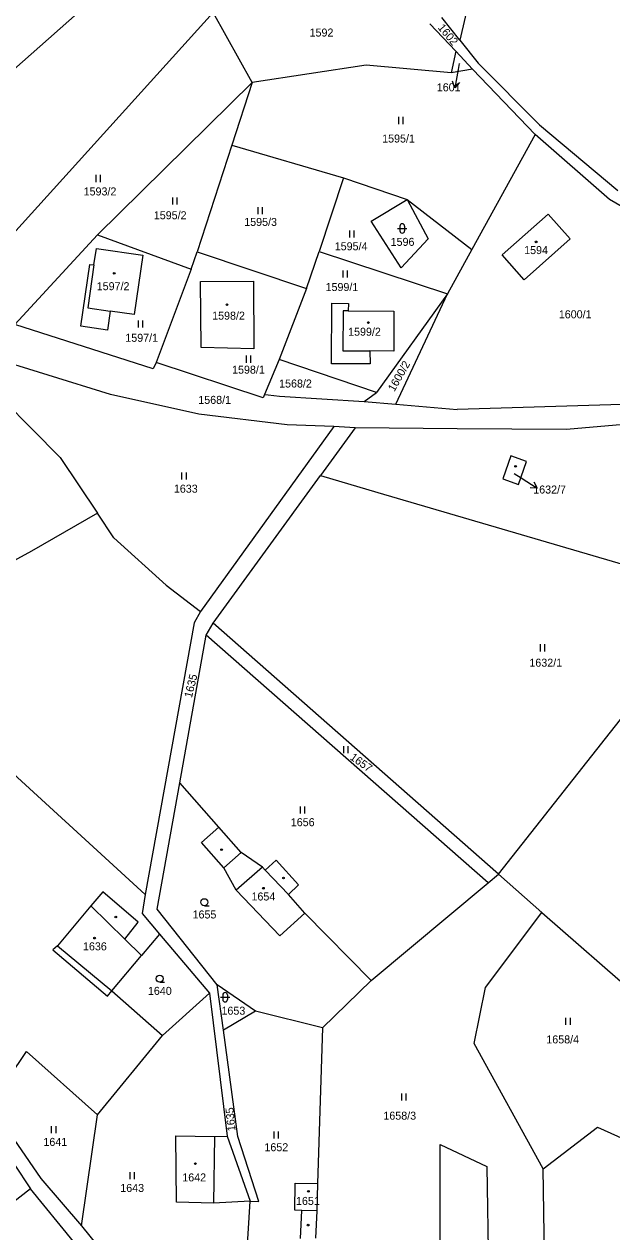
# Model space of a CAD drawing. Extents: x -670359 to -668019, y -978807 to -976674.
# Drawn here: x -669263 to -669138.3, y -978307.2 to -978050.6 of the extents above; entities that cross this region are included whole.
import ezdxf

# ---------------------------------------------------------------- set-up
doc = ezdxf.new("R2010")
doc.units = 0
for name, color, linetype in [('Hranice parcel', 7, 'Continuous'), ('Parcelní čísla', 7, 'Continuous'), ('Vnitřní kresba', 7, 'Continuous'), ('Značky budov', 7, 'Continuous'), ('Značky kultur', 7, 'Continuous')]:
    doc.layers.add(name, color=color, linetype=linetype)

msp = doc.modelspace()

# ---------------------------------------------------------------- linework, layer by layer
at = {"layer": 'Hranice parcel'}
for p, q in [((-669197.76, -978122.79), (-669197.75, -978109.9)), ((-669197.75, -978109.9), (-669194.2, -978109.99)), ((-669194.2, -978109.99), (-669194.25, -978111.55)), ((-669184.14, -978131.34), (-669173.14, -978107.89)), ((-669194.25, -978111.55), (-669184.52, -978111.61)), ((-669184.52, -978111.61), (-669184.54, -978120.13)), ((-669184.54, -978120.13), (-669189.62, -978120.06)), ((-669189.62, -978120.06), (-669189.6, -978122.82)), ((-669189.6, -978122.82), (-669197.76, -978122.79)), ((-669190.87, -978130.76), (-669184.14, -978131.34)), ((-669184.14, -978131.34), (-669171.08, -978132.47)), ((-669153.11, -978239.3), (-669162.35, -978231.21)), ((-669165.06, -978255.27), (-669153.11, -978239.3)), ((-669153.11, -978239.3), (-669114.29, -978273.3)), ((-669167.46, -978267.15), (-669165.06, -978255.27)), ((-669152.85, -978293.75), (-669167.46, -978267.15))]:
    msp.add_line(p, q, dxfattribs=at)
for points in [[(-669162.99, -978021.31), (-669170.57, -978054.01)], [(-669234.55, -978033), (-669307.7, -978097.77)], [(-669280.17, -978111.46), (-669222.94, -978048.17)], [(-669214.62, -978063.05), (-669222.94, -978048.17)], [(-669171.4, -978056.4), (-669176.94, -978050.58)], [(-669170.57, -978054.01), (-669174.37, -978049.25)], [(-669171.4, -978056.4), (-669172.41, -978060.95)], [(-669167.84, -978060.2), (-669171.4, -978056.4)], [(-669170.57, -978054.01), (-669166.62, -978058.93)], [(-669166.62, -978058.93), (-669153.63, -978072.03)], [(-669190.4, -978059.32), (-669214.62, -978063.05)], [(-669172.41, -978060.95), (-669190.4, -978059.32)], [(-669167.84, -978060.2), (-669172.41, -978060.95)], [(-669154.54, -978074.1), (-669167.84, -978060.2)], [(-669214.62, -978063.05), (-669247.46, -978095.41)], [(-669214.62, -978063.05), (-669218.93, -978076.33)], [(-669154.54, -978074.1), (-669167.96, -978098.48)], [(-669138.75, -978087.87), (-669154.54, -978074.1)], [(-669153.63, -978072.03), (-669136.97, -978085.97)], [(-669218.93, -978076.33), (-669226.28, -978099)], [(-669218.93, -978076.33), (-669195.22, -978083.25)], [(-669195.22, -978083.25), (-669200.43, -978098.96)], [(-669195.22, -978083.25), (-669181.74, -978087.88)], [(-669189.39, -978092.52), (-669181.74, -978087.88)], [(-669181.74, -978087.88), (-669167.96, -978098.48)], [(-669181.74, -978087.88), (-669177.26, -978096.25)], [(-669123.24, -978096.91), (-669138.75, -978087.87)], [(-669161.57, -978099.66), (-669151.75, -978090.97)], [(-669151.75, -978090.97), (-669147.09, -978096.22)], [(-669183.01, -978102.43), (-669189.39, -978092.52)], [(-669247.46, -978095.41), (-669265.03, -978114.42)], [(-669247.46, -978095.41), (-669227.6, -978102.67)], [(-669177.26, -978096.25), (-669183.01, -978102.43)], [(-669147.09, -978096.22), (-669156.86, -978104.95)], [(-669248.23, -978101.77), (-669247.72, -978098.27)], [(-669247.72, -978098.27), (-669237.84, -978099.69)], [(-669237.84, -978099.69), (-669239.66, -978112.34)], [(-669227.6, -978102.67), (-669226.28, -978099)], [(-669226.28, -978099), (-669203.07, -978106.77)], [(-669203.07, -978106.77), (-669200.43, -978098.96)], [(-669200.43, -978098.96), (-669173.14, -978107.89)], [(-669167.96, -978098.48), (-669173.14, -978107.89)], [(-669156.86, -978104.95), (-669161.57, -978099.66)], [(-669251.01, -978114.77), (-669249.11, -978101.66)], [(-669249.11, -978101.66), (-669248.23, -978101.77)], [(-669227.6, -978102.67), (-669235.02, -978122.5)], [(-669225.63, -978105.33), (-669214.34, -978105.21)], [(-669214.34, -978105.21), (-669214.29, -978119.57)], [(-669225.46, -978119.29), (-669225.63, -978105.33)], [(-669203.07, -978106.77), (-669208.91, -978121.9)], [(-669173.14, -978107.89), (-669188.25, -978128.85)], [(-669244.82, -978111.6), (-669245.38, -978115.62)], [(-669239.66, -978112.34), (-669244.82, -978111.6)], [(-669235.67, -978123.85), (-669265.03, -978114.42)], [(-669245.38, -978115.62), (-669251.01, -978114.77)], [(-669214.29, -978119.57), (-669225.46, -978119.29)], [(-669244.69, -978129.28), (-669271.26, -978121.07)], [(-669235.02, -978122.5), (-669235.67, -978123.85)], [(-669212.28, -978130.03), (-669235.02, -978122.5)], [(-669208.91, -978121.9), (-669211.98, -978129.3)], [(-669188.25, -978128.85), (-669208.91, -978121.9)], [(-669273.38, -978124.57), (-669255.4, -978142.68)], [(-669225.93, -978133.48), (-669244.69, -978129.28)], [(-669211.98, -978129.3), (-669212.28, -978130.03)], [(-669211.98, -978129.3), (-669211.25, -978129.4), (-669208.86, -978129.64), (-669190.87, -978130.76)], [(-669190.87, -978130.76), (-669188.25, -978128.85)], [(-669136.17, -978131.41), (-669171.08, -978132.47)], [(-669207.22, -978135.76), (-669225.93, -978133.48)], [(-669197.3, -978136.11), (-669207.22, -978135.76)], [(-669135.74, -978135.65), (-669147.91, -978136.72)], [(-669197.3, -978136.11), (-669225.57, -978175.39)], [(-669192.74, -978136.4), (-669200.12, -978146.54)], [(-669192.74, -978136.4), (-669197.3, -978136.11)], [(-669171.13, -978136.63), (-669192.74, -978136.4)], [(-669147.91, -978136.72), (-669171.13, -978136.63)], [(-669255.4, -978142.68), (-669247.51, -978154.5)], [(-669159.68, -978142.35), (-669161.4, -978147.2)], [(-669156.38, -978143.57), (-669159.68, -978142.35)], [(-669158.06, -978148.39), (-669156.38, -978143.57)], [(-669222.95, -978177.9), (-669200.12, -978146.54)], [(-669200.12, -978146.54), (-669187.92, -978150.12)], [(-669161.4, -978147.2), (-669158.06, -978148.39)], [(-669187.92, -978150.12), (-669122.96, -978169.18)], [(-669247.51, -978154.5), (-669261.49, -978162.57)], [(-669244.01, -978159.74), (-669247.51, -978154.5)], [(-669244.01, -978159.74), (-669232.87, -978169.8)], [(-669261.49, -978162.57), (-669288.18, -978177.2)], [(-669232.87, -978169.8), (-669225.57, -978175.39)], [(-669225.57, -978175.39), (-669226.95, -978177.78)], [(-669226.95, -978177.78), (-669237.33, -978235.49)], [(-669224.42, -978180.44), (-669222.95, -978177.9)], [(-669162.35, -978231.21), (-669222.95, -978177.9)], [(-669230.01, -978211.78), (-669224.42, -978180.44)], [(-669164.49, -978233), (-669224.42, -978180.44)], [(-669162.35, -978231.21), (-669134.61, -978195.97)], [(-669271.34, -978204.41), (-669237.33, -978235.49)], [(-669234.8, -978238.64), (-669230.01, -978211.78)], [(-669221.7, -978221.23), (-669230.01, -978211.78)], [(-669225.38, -978224.47), (-669221.7, -978221.23)], [(-669216.98, -978226.6), (-669221.7, -978221.23)], [(-669220.66, -978229.84), (-669225.38, -978224.47)], [(-669212.45, -978229.68), (-669216.98, -978226.6)], [(-669209.56, -978228.2), (-669211.9, -978230.33)], [(-669204.81, -978233.45), (-669209.56, -978228.2)], [(-669218.03, -978234.58), (-669220.66, -978229.84)], [(-669211.9, -978230.33), (-669212.45, -978229.68)], [(-669206.91, -978235.5), (-669204.81, -978233.45)], [(-669189.33, -978253.77), (-669164.49, -978233)], [(-669164.49, -978233), (-669162.35, -978231.21)], [(-669246.37, -978234.92), (-669248.88, -978237.93)], [(-669238.83, -978241.4), (-669246.37, -978234.92)], [(-669237.33, -978235.49), (-669238.01, -978239.57)], [(-669208.76, -978244.28), (-669218.03, -978234.58)], [(-669203.43, -978239.46), (-669206.91, -978235.5)], [(-669248.88, -978237.93), (-669255.94, -978246.41)], [(-669238.01, -978239.57), (-669234.31, -978243.93)], [(-669222.08, -978254.7), (-669234.8, -978238.64)], [(-669203.43, -978239.46), (-669208.76, -978244.28)], [(-669189.33, -978253.77), (-669203.43, -978239.46)], [(-669241.67, -978244.97), (-669238.83, -978241.4)], [(-669238.11, -978248.44), (-669241.67, -978244.97)], [(-669234.31, -978243.93), (-669238.11, -978248.44)], [(-669234.31, -978243.93), (-669223.7, -978256.44)], [(-669255.94, -978246.41), (-669256.99, -978247.28)], [(-669256.99, -978247.28), (-669245.32, -978257.08)], [(-669244.43, -978255.97), (-669238.11, -978248.44)], [(-669199.68, -978263.84), (-669189.33, -978253.77)], [(-669245.32, -978257.08), (-669244.43, -978255.97)], [(-669244.43, -978255.97), (-669233.64, -978265.45)], [(-669233.64, -978265.45), (-669223.7, -978256.44)], [(-669223.7, -978256.44), (-669219.94, -978286.87)], [(-669213.9, -978260.3), (-669222.08, -978254.7)], [(-669220.74, -978264.31), (-669222.08, -978254.7)], [(-669213.9, -978260.3), (-669220.74, -978264.31)], [(-669199.68, -978263.84), (-669213.9, -978260.3)], [(-669199.68, -978263.84), (-669200.76, -978296.92)], [(-669247.51, -978282.34), (-669233.64, -978265.45)], [(-669217.7, -978286.9), (-669220.74, -978264.31)], [(-669270.3, -978280.25), (-669262.58, -978268.89)], [(-669262.58, -978268.89), (-669247.51, -978282.34)], [(-669270.3, -978280.25), (-669259.5, -978295.8)], [(-669272.16, -978282.31), (-669261.68, -978298.02)], [(-669250.88, -978305.89), (-669247.51, -978282.34)], [(-669230.83, -978286.75), (-669222.66, -978286.92)], [(-669230.73, -978300.83), (-669230.83, -978286.75)], [(-669222.66, -978286.92), (-669219.94, -978286.87)], [(-669219.94, -978286.87), (-669215.04, -978300.68)], [(-669213.2, -978300.7), (-669217.7, -978286.9)], [(-669152.85, -978293.75), (-669141.31, -978284.92)], [(-669141.31, -978284.92), (-669117.25, -978295.74)], [(-669174.73, -978288.64), (-669164.78, -978293.31)], [(-669174.69, -978337.35), (-669174.73, -978288.64)], [(-669164.78, -978293.31), (-669164.12, -978337.46)], [(-669152.14, -978339.99), (-669152.85, -978293.75)], [(-669259.5, -978295.8), (-669250.88, -978305.89)], [(-669205.54, -978302.54), (-669205.48, -978296.79)], [(-669205.48, -978296.79), (-669200.76, -978296.92)], [(-669200.76, -978296.92), (-669200.9, -978302.67)], [(-669261.68, -978298.02), (-669271.45, -978305.59)], [(-669252.6, -978309.23), (-669261.68, -978298.02)], [(-669222.81, -978301.08), (-669230.73, -978300.83)], [(-669215.04, -978300.68), (-669222.81, -978301.08)], [(-669217.26, -978336.41), (-669215.04, -978300.68)], [(-669215.04, -978300.68), (-669213.2, -978300.7)], [(-669204.1, -978302.64), (-669205.54, -978302.54)], [(-669204.4, -978308.56), (-669204.1, -978302.64)], [(-669200.9, -978302.67), (-669201.2, -978308.51)], [(-669250.88, -978305.89), (-669233.26, -978327.76)]]:
    msp.add_lwpolyline(points, dxfattribs=at)
at = {"layer": 'Parcelní čísla'}
for p, q in [((-669170.67, -978058.99), (-669170.89, -978060.25)), ((-669170.63, -978063.04), (-669171.59, -978064.19)), ((-669159.02, -978146.05), (-669157.48, -978147.03)), ((-669154.8, -978147.85), (-669154.11, -978149.18))]:
    msp.add_line(p, q, dxfattribs=at)
for points in [[(-669170.89, -978060.25), (-669171.59, -978064.19), (-669172.1, -978062.78)], [(-669157.48, -978147.03), (-669154.11, -978149.18), (-669155.6, -978149.11)]]:
    msp.add_lwpolyline(points, dxfattribs=at)
at = {"layer": 'Vnitřní kresba'}
for p, q in [((-669195.3, -978111.54), (-669195.35, -978120)), ((-669194.25, -978111.55), (-669195.3, -978111.54)), ((-669195.35, -978120), (-669189.62, -978120.06))]:
    msp.add_line(p, q, dxfattribs=at)
for points in [[(-669248.23, -978101.77), (-669249.54, -978110.92)], [(-669249.54, -978110.92), (-669244.82, -978111.6)], [(-669216.98, -978226.6), (-669220.66, -978229.84)], [(-669212.45, -978229.68), (-669218.03, -978234.58)], [(-669211.9, -978230.33), (-669206.91, -978235.5)], [(-669248.88, -978237.93), (-669241.67, -978244.97)], [(-669255.94, -978246.41), (-669244.43, -978255.97)], [(-669222.66, -978286.92), (-669222.81, -978301.08)], [(-669200.9, -978302.67), (-669204.1, -978302.64)]]:
    msp.add_lwpolyline(points, dxfattribs=at)
at = {"layer": 'Značky budov'}
for centre in [(-669154.34, -978096.88), (-669243.92, -978103.56), (-669219.98, -978110.24), (-669189.96, -978114.02), (-669158.71, -978144.58), (-669212.24, -978234.18), (-669248.1, -978244.77), (-669226.7, -978292.68), (-669202.68, -978298.56)]:
    msp.add_circle(centre, 0.175, dxfattribs=at)
at = {"layer": 'Značky kultur'}
for p, q in [((-669183.58, -978070.35), (-669183.58, -978071.85)), ((-669182.58, -978071.85), (-669182.58, -978070.35)), ((-669247.81, -978082.67), (-669247.81, -978084.17)), ((-669246.81, -978084.17), (-669246.81, -978082.67)), ((-669231.54, -978087.46), (-669231.54, -978088.96)), ((-669230.54, -978088.96), (-669230.54, -978087.46)), ((-669213.41, -978089.51), (-669213.41, -978091.01)), ((-669212.41, -978091.01), (-669212.41, -978089.51)), ((-669193.97, -978094.48), (-669193.97, -978095.98)), ((-669192.97, -978095.98), (-669192.97, -978094.48)), ((-669183.77, -978094.03), (-669181.77, -978094.03)), ((-669183.27, -978093.53), (-669183.27, -978094.53)), ((-669182.27, -978093.53), (-669182.27, -978094.53)), ((-669195.38, -978102.93), (-669195.38, -978104.43)), ((-669194.38, -978104.43), (-669194.38, -978102.93)), ((-669238.86, -978113.58), (-669238.86, -978115.08)), ((-669237.86, -978115.08), (-669237.86, -978113.58)), ((-669215.94, -978121.05), (-669215.94, -978122.55)), ((-669214.94, -978122.55), (-669214.94, -978121.05)), ((-669229.61, -978145.84), (-669229.61, -978147.34)), ((-669228.61, -978147.34), (-669228.61, -978145.84)), ((-669153.51, -978182.36), (-669153.51, -978183.86)), ((-669152.51, -978183.86), (-669152.51, -978182.36)), ((-669195.25, -978203.99), (-669195.25, -978205.49)), ((-669194.25, -978205.49), (-669194.25, -978203.99)), ((-669204.47, -978216.8), (-669204.47, -978218.3)), ((-669203.47, -978218.3), (-669203.47, -978216.8)), ((-669224.79, -978237.9), (-669223.79, -978237.9)), ((-669234.27, -978254.13), (-669233.27, -978254.13)), ((-669221.37, -978257.34), (-669219.37, -978257.34)), ((-669220.87, -978256.84), (-669220.87, -978257.84)), ((-669219.87, -978256.84), (-669219.87, -978257.84)), ((-669148.07, -978261.7), (-669148.07, -978263.2)), ((-669147.07, -978263.2), (-669147.07, -978261.7)), ((-669182.92, -978277.77), (-669182.92, -978279.27)), ((-669181.92, -978279.27), (-669181.92, -978277.77)), ((-669257.28, -978284.71), (-669257.28, -978286.21)), ((-669256.28, -978286.21), (-669256.28, -978284.71)), ((-669210.03, -978285.84), (-669210.03, -978287.34)), ((-669209.03, -978287.34), (-669209.03, -978285.84)), ((-669240.64, -978294.49), (-669240.64, -978295.99)), ((-669239.64, -978295.99), (-669239.64, -978294.49))]:
    msp.add_line(p, q, dxfattribs=at)
for centre, radius in [((-669154.34, -978096.88), 0.175), ((-669243.92, -978103.56), 0.175), ((-669219.98, -978110.24), 0.175), ((-669189.96, -978114.02), 0.175), ((-669158.71, -978144.58), 0.175), ((-669221.14, -978225.99), 0.175), ((-669207.98, -978231.99), 0.175), ((-669212.24, -978234.18), 0.175), ((-669224.79, -978237.15), 0.75), ((-669243.59, -978240.29), 0.175), ((-669248.1, -978244.77), 0.175), ((-669234.27, -978253.38), 0.75), ((-669226.7, -978292.68), 0.175), ((-669202.68, -978298.56), 0.175), ((-669202.75, -978305.73), 0.175)]:
    msp.add_circle(centre, radius, dxfattribs=at)
for centre, start, end in [((-669182.77, -978093.53), 0, 180), ((-669182.77, -978094.53), 180, 0), ((-669220.37, -978256.84), 0, 180), ((-669220.37, -978257.84), 180, 0)]:
    msp.add_arc(centre, 0.5, start, end, dxfattribs=at)

# ---------------------------------------------------------------- texts
at = {"layer": 'Parcelní čísla'}
for s, rotation, p in [('1602', 310.0528, (-669175.32, -978051.45)), ('1600/2', 60.3, (-669184.45, -978128.83)), ('1635', 76.3043, (-669227.44, -978193.85)), ('1657', 324.7067, (-669194.02, -978206.69)), ('1635', 95.3082, (-669218.16, -978285.7))]:
    msp.add_text(s, height=1.7, rotation=rotation, dxfattribs=at).set_placement(p)
for s, height, p in [('1592', 1.7, (-669202.44, -978053.27)), ('1601', 0.1, (-669170.67, -978058.99)), ('1601', 1.7, (-669175.43, -978064.9)), ('1595/1', 1.7, (-669187.03, -978075.78)), ('1593/2', 1.7, (-669250.42, -978087.02)), ('1595/2', 1.7, (-669235.52, -978092.08)), ('1595/3', 1.7, (-669216.32, -978093.5)), ('1595/4', 1.7, (-669197.1, -978098.67)), ('1596', 1.7, (-669185.23, -978097.73)), ('1594', 1.7, (-669156.88, -978099.48)), ('1597/2', 1.7, (-669247.64, -978107.15)), ('1599/1', 1.7, (-669199.05, -978107.33)), ('1598/2', 1.7, (-669223.13, -978113.41)), ('1600/1', 1.7, (-669149.52, -978113.12)), ('1599/2', 1.7, (-669194.26, -978116.82)), ('1597/1', 1.7, (-669241.57, -978118.11)), ('1598/1', 1.7, (-669218.9, -978124.88)), ('1568/2', 1.7, (-669208.91, -978127.82)), ('1568/1', 1.7, (-669226.07, -978131.3)), ('1632/7', 0.1, (-669159.02, -978146.05)), ('1633', 1.7, (-669231.26, -978150.16)), ('1632/7', 1.7, (-669154.95, -978150.34)), ('1632/1', 1.7, (-669155.77, -978187.12)), ('1656', 1.7, (-669206.43, -978221)), ('1654', 1.7, (-669214.78, -978236.78)), ('1655', 1.7, (-669227.29, -978240.6)), ('1636', 1.7, (-669250.56, -978247.37)), ('1640', 1.7, (-669236.77, -978256.83)), ('1653', 1.7, (-669221.15, -978261.04)), ('1658/4', 1.7, (-669152.17, -978267.14)), ('1658/3', 1.7, (-669186.77, -978283.34)), ('1641', 1.7, (-669258.96, -978288.91)), ('1652', 1.7, (-669212.03, -978290.04)), ('1642', 1.7, (-669229.47, -978296.45)), ('1643', 1.7, (-669242.64, -978298.69)), ('1651', 1.7, (-669205.33, -978301.45))]:
    msp.add_text(s, height=height, dxfattribs=at).set_placement(p)

doc.saveas('drawing.dxf')
